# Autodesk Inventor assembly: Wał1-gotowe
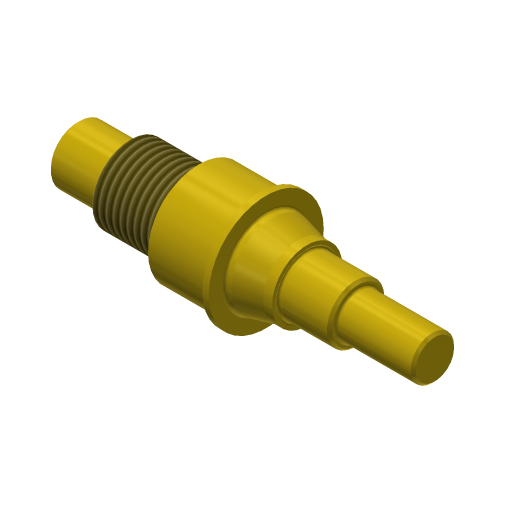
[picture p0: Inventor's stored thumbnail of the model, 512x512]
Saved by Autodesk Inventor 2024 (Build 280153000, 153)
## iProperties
Company: ATC
ClientObjectVersion: 1
Created: 2023-03
Part Number: Wał1-gotowe
Document SubType Name: Assembly
Designer: Andrzej Jaskulski
Stock Number: Wał1-gotowe
Checked By: A.J.
Engr Approved By: Andrzej Jaskulski
Mfg Approved By: Andrzej Jaskulski
Authority: A.J.
Title: A.J.: Kurs R2024-MEP
Author: Andrzej Jaskulski
Revision Number: 1/24
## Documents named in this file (2)
- C:\Users\AndJas\Documents\R2024-MEP\Obszar roboczy\PZ\GOTOWE\Wał1-gotowe.iam
- C:\Users\AndJas\Documents\R2024-MEP\Obszar roboczy\PZ\GOTOWE\Wał1-gotowe.ipt
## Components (1 placed, 1 different names)
1. Wał:1
